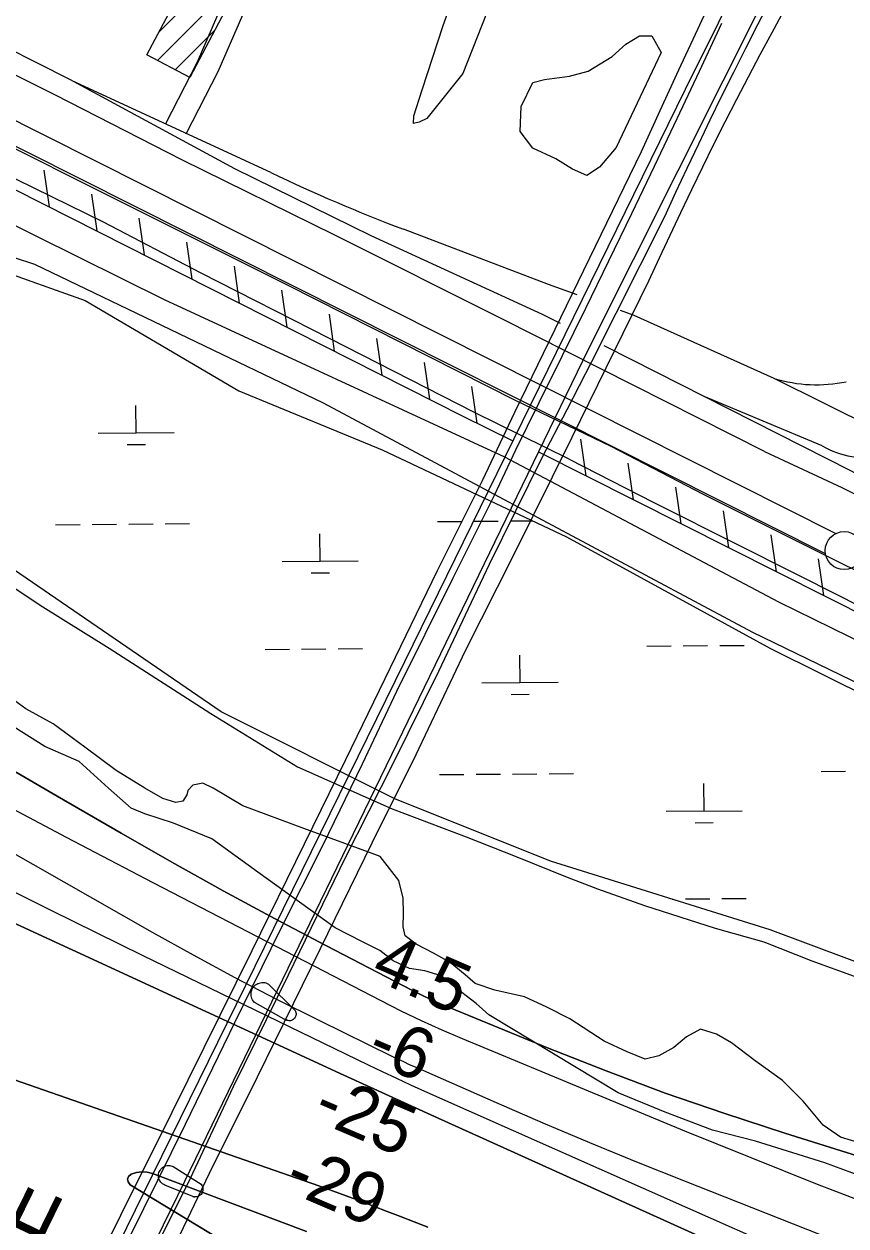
# Model space of a CAD drawing. Extents: x 3567028 to 3605064, y 510945 to 536587.
# Drawn here: x 3584827 to 3585908, y 526486 to 528066 of the extents above; entities that cross this region are included whole.
import ezdxf

# ---------------------------------------------------------------- set-up
doc = ezdxf.new("R2010")
doc.units = 0
for name, color, linetype in [('V-BLDG-OTLN', 7, 'Continuous'), ('V-BRDG-IDEN', 7, 'Continuous'), ('V-BRDG-OTLN', 7, 'Continuous'), ('V-CHAN-DOCK', 7, 'Continuous'), ('V-FLOD-BASE', 7, 'Continuous'), ('V-LEVE-TOET', 7, 'Continuous'), ('V-RIVR-EDGE', 7, 'Continuous'), ('V-RIVR-RANG', 7, 'Continuous'), ('V-ROAD-CNTR', 7, 'Continuous'), ('V-RRAP-FSHR', 7, 'Continuous'), ('V-SITE-VEGE', 7, 'Continuous'), ('V-SURV-LINE', 7, 'Continuous'), ('V-TOPO-DPTH', 7, 'Continuous'), ('V-TOPO-MINR', 7, 'Continuous'), ('V-TOPO-WATR', 7, 'Continuous'), ('V-WETL-SWMP', 7, 'Continuous')]:
    doc.layers.add(name, color=color, linetype=linetype)

msp = doc.modelspace()

# ---------------------------------------------------------------- linework, layer by layer
at = {"layer": 'V-BLDG-OTLN'}
for p, q in [((3585004, 528054.7), (3585074.8, 528125.5)), ((3585002.6, 528017.9), (3585089.1, 528104.4)), ((3585025.7, 528005.7), (3585077.9, 528057.8))]:
    msp.add_line(p, q, dxfattribs=at)
msp.add_lwpolyline([(3585099.6, 528098.9), (3585045, 527995.5), (3584988.5, 528025.3), (3585042.7, 528127.9)], dxfattribs=at)
at = {"layer": 'V-BRDG-OTLN'}
for points in [[(3584878.4, 526347.8), (3584954.3, 526500.4), (3585022, 526635.6), (3585126.9, 526848.3), (3585195.7, 526988.4), (3585250.2, 527099), (3585302.1, 527205.6), (3585370.9, 527347.8), (3585430, 527465.9), (3585472.3, 527555.5), (3585638.8, 527898.5), (3585663.3, 527952.1), (3585688, 528005.7), (3585712.8, 528059.2), (3585737.7, 528112.6)], [(3585439.1, 527355.7), (3585508.3, 527496.1), (3585541, 527559.3), (3585573.5, 527622.5), (3585605.8, 527685.9), (3585637.8, 527749.4), (3585669.5, 527813), (3585684.2, 527844.8), (3585699, 527876.6), (3585714.1, 527908.2), (3585729.3, 527939.8), (3585744.7, 527971.3), (3585760.3, 528002.7), (3585776, 528034), (3585792, 528065.3), (3585808.1, 528096.4)], [(3585826, 528083.5), (3585810.2, 528054.4), (3585794.5, 528025.2), (3585779, 527995.9), (3585763.7, 527966.5), (3585748.6, 527937), (3585733.7, 527907.3), (3585719, 527877.6), (3585704.5, 527847.8), (3585690.1, 527817.9), (3585676, 527787.9), (3585662, 527757.9), (3585648.3, 527727.7), (3585547.4, 527522.4), (3585470, 527366.7), (3585407.3, 527242.1), (3585342.1, 527105.4), (3585284.6, 526989.3), (3585216.3, 526850.2), (3585133.8, 526681.5), (3585070.7, 526554.9), (3585007, 526422.2)], [(3584927.4, 526393.9), (3584984.5, 526509.1), (3585039.6, 526619.8), (3585104.2, 526753.3), (3585163.8, 526874.9), (3585220.4, 526987.1), (3585271.9, 527093.3), (3585317.4, 527189.1), (3585391.1, 527338.1), (3585445.7, 527446.8), (3585473.5, 527506.3), (3585504.4, 527568.2), (3585535.1, 527630.2), (3585565.6, 527692.3), (3585596, 527754.5), (3585626.1, 527816.7), (3585656, 527879.1), (3585685.8, 527941.6), (3585715.3, 528004.1), (3585744.7, 528066.8)], [(3584983.4, 526423.4), (3585042.5, 526541.5), (3585102.6, 526669.6), (3585174.9, 526816.1), (3585249.6, 526970.5), (3585311.8, 527093.1), (3585372.4, 527215.2), (3585439.1, 527355.7)]]:
    msp.add_lwpolyline(points, dxfattribs=at)
at = {"layer": 'V-CHAN-DOCK'}
for points in [[(3585172.3, 526756.3), (3585130.9, 526779.2), (3585129.6, 526780.4), (3585128.5, 526781.8), (3585127.5, 526783.4), (3585126.7, 526785), (3585126.1, 526786.7), (3585125.8, 526788.5), (3585125.6, 526790.3), (3585125.6, 526792.1), (3585125.9, 526793.9), (3585126.4, 526795.6), (3585127, 526797.3), (3585127.9, 526798.9), (3585129, 526800.4), (3585130.2, 526801.7), (3585131.5, 526802.9), (3585133, 526803.9), (3585134.6, 526804.8), (3585136.3, 526805.4), (3585138.1, 526805.8), (3585139.9, 526806.1), (3585141.7, 526806.1), (3585143.5, 526805.9), (3585145.2, 526805.5), (3585146.9, 526804.9), (3585148.6, 526804.1), (3585182.7, 526770.3), (3585183.5, 526769.2), (3585184.1, 526768), (3585184.5, 526766.7), (3585184.7, 526765.4), (3585184.8, 526764.1), (3585184.6, 526762.8), (3585184.2, 526761.5), (3585183.6, 526760.3), (3585182.9, 526759.2), (3585182, 526758.2), (3585181, 526757.4), (3585179.8, 526756.7), (3585178.6, 526756.2), (3585177.3, 526755.9), (3585175.9, 526755.9), (3585174.6, 526756), (3585173.3, 526756.3), (3585172.1, 526756.8)], [(3585051.2, 526523.9), (3585012.2, 526539.7), (3585010.7, 526540.4), (3585009.3, 526541.3), (3585008.1, 526542.4), (3585006.9, 526543.6), (3585005.9, 526545), (3585005.1, 526546.4), (3585004.5, 526548), (3585004.1, 526549.6), (3585003.9, 526551.2), (3585003.9, 526552.9), (3585004.1, 526554.6), (3585004.5, 526556.2), (3585005.1, 526557.8), (3585005.9, 526559.2), (3585006.8, 526560.6), (3585007.9, 526561.8), (3585009.2, 526562.9), (3585010.6, 526563.8), (3585012.1, 526564.6), (3585013.7, 526565.1), (3585015.3, 526565.5), (3585017, 526565.6), (3585018.7, 526565.6), (3585020.3, 526565.3), (3585021.9, 526564.8), (3585023.4, 526564.1), (3585059.8, 526540.9), (3585060.7, 526539.7), (3585061.5, 526538.4), (3585062, 526537), (3585062.3, 526535.6), (3585062.4, 526534.1), (3585062.3, 526532.7), (3585061.9, 526531.2), (3585061.4, 526529.9), (3585060.7, 526528.6), (3585059.8, 526527.4), (3585058.7, 526526.4), (3585057.5, 526525.6), (3585056.2, 526524.9), (3585054.8, 526524.5), (3585053.3, 526524.2), (3585051.9, 526524.2), (3585050.4, 526524.4), (3585049, 526524.8)]]:
    msp.add_lwpolyline(points, close=True, dxfattribs=at)
at = {"layer": 'V-FLOD-BASE'}
for points in [[(3582067.9, 529075.6), (3582390.6, 528943.1), (3582813.9, 528766.3), (3583236.6, 528590.2), (3583544.8, 528463.3), (3583628.2, 528428), (3583676.5, 528412.7), (3583853.7, 528359.9), (3583920.6, 528338.4), (3583993, 528309.9), (3584101.2, 528261.4), (3584270.1, 528174.8), (3584552.1, 528034.2), (3584908.4, 527855.4), (3585173.1, 527723.1), (3585473, 527571.4), (3585598.5, 527510.8)], [(3585598.5, 527510.8), (3585720.1, 527448.1), (3585840.9, 527387.5), (3585981.5, 527317.2), (3586090.3, 527262.9), (3586177.2, 527217.9), (3586257, 527178), (3586332.7, 527140.1), (3586408, 527101), (3586484.1, 527063.1), (3586580.5, 527015.9), (3586678.1, 526965.9), (3586788.5, 526910.3), (3586899.4, 526854.4), (3587009.8, 526797.2), (3587129.4, 526739.1), (3587234.4, 526686.1), (3587359.8, 526623.8)]]:
    msp.add_lwpolyline(points, dxfattribs=at)
at = {"layer": 'V-LEVE-TOET'}
for points in [[(3585800.6, 527504), (3585456.1, 527677.8), (3585235.8, 527788.4), (3585034.7, 527887.3), (3584868.3, 527972.4), (3584648.8, 528081.5), (3584466.7, 528175.6), (3584328.5, 528266.6), (3584153.9, 528352.1), (3584057.8, 528396.8), (3583943.7, 528438.9), (3583778.9, 528490.4), (3583702.3, 528503.4), (3583587.4, 528539.2), (3583433.9, 528602.8), (3583298.3, 528659.7), (3583120.2, 528732.7), (3582964.7, 528798.7), (3582761.2, 528883.9), (3582560, 528967.9), (3582369.7, 529046.8), (3582210, 529111.6), (3582064.8, 529177.9)], [(3585544, 527493.7), (3585419.4, 527555.3), (3585229.6, 527652.2), (3585059.3, 527738.9), (3584931.6, 527805.6), (3584725.8, 527906.4), (3584560.1, 527988.8), (3584318.8, 528108.5), (3584129.3, 528205.4), (3584045.3, 528249.3), (3583951.6, 528290.5), (3583911, 528308.6), (3583847.3, 528329.4), (3583708.6, 528369.5)], [(3585544, 527493.7), (3585654.1, 527437.3), (3585767.8, 527380.5), (3585904.3, 527311.5), (3586020.1, 527251.8), (3586143.8, 527192.4), (3586262.9, 527128.9), (3586361.8, 527080.1), (3586459.4, 527034.2), (3586528.1, 526999.7), (3586615.8, 526956.3), (3586715, 526906.3), (3586804.8, 526858.3), (3586895.4, 526812.9), (3586998.8, 526760.7), (3587096, 526711.1), (3587210.1, 526655.1), (3587296.2, 526610.9)], [(3585800.6, 527504), (3585902.4, 527456.8), (3586009.5, 527403.8), (3586145.2, 527337.3), (3586258.5, 527279.2), (3586373.1, 527220.3), (3586475.7, 527168.6), (3586573.3, 527118.9), (3586670.1, 527068), (3586785, 527007.1), (3586874.3, 526955.4), (3586919, 526931), (3586960, 526913.3), (3586991, 526902.3), (3587048.1, 526880.7), (3587077.1, 526867.7), (3587199.5, 526801.3), (3587323.2, 526735.3)]]:
    msp.add_lwpolyline(points, dxfattribs=at)
at = {"layer": 'V-RIVR-EDGE'}
for points in [[(3585334, 526824.6), (3585312.6, 526834.4), (3585294.8, 526848), (3585272.2, 526859.7), (3585236.1, 526878.1), (3585134.5, 526951.3), (3585074, 526995), (3585023.8, 527015.3), (3584985.8, 527027.7), (3584968.1, 527035), (3584938.1, 527061.5), (3584899.6, 527096.5), (3584854.3, 527116.2), (3584753.4, 527179.6)], [(3586130.9, 526467.9), (3586052.5, 526500.5), (3585992.5, 526531.3), (3585915.4, 526556), (3585879.9, 526569), (3585788.7, 526597.4), (3585732.3, 526612.2), (3585669.9, 526635.7), (3585608.1, 526660.9), (3585438, 526763.7), (3585421.5, 526778.4), (3585389.7, 526803), (3585375.6, 526814.7), (3585354.2, 526821.5), (3585334, 526824.6)]]:
    msp.add_lwpolyline(points, dxfattribs=at)
at = {"layer": 'V-ROAD-CNTR'}
for points in [[(3587306.2, 531259), (3586754.9, 530134.8), (3586369, 529338.2), (3585957, 528504.3), (3585696.4, 527979.8), (3585493, 527565.5)], [(3587344.1, 531242.8), (3586812, 530145.3), (3586563.1, 529653), (3586317.5, 529145.1), (3586066.9, 528651.8), (3585863.7, 528225.8), (3585568.9, 527637.9), (3585525.1, 527547.7)], [(3584887.2, 527992.8), (3584760.1, 528057), (3584640.4, 528117.2), (3584312.5, 528284.6), (3584113.6, 528394.3)], [(3585040.2, 527921.4), (3585082.3, 528003.3), (3585130.8, 528115.4), (3585145.2, 528145), (3585155.2, 528170.5), (3585161.3, 528193.7), (3585161.5, 528216.6), (3585153.4, 528233.4), (3585133.7, 528249.1), (3585112.6, 528248.4), (3585093.8, 528246.3), (3585078.4, 528228.2), (3585069.9, 528210.7), (3585068.9, 528190.9), (3585070.8, 528172.1), (3585079.4, 528151.8), (3585089.1, 528135.1), (3585100, 528120.8)], [(3585013.5, 527935.1), (3585055.2, 528016.1), (3585100.4, 528120.7)], [(3585532.4, 527672.1), (3585508.9, 527684.1), (3585283.4, 527787.6), (3585104.1, 527875.4), (3584887.2, 527992.8)], [(3585151.7, 527870.8), (3584890.6, 527991)], [(3585554.3, 527710.1), (3585516.8, 527723.7), (3585326, 527796.1)], [(3585813.5, 527600), (3585629.1, 527682.8), (3585611.5, 527689.3)], [(3586903, 526969), (3586583.5, 527131.1), (3586151, 527350.4), (3585914.1, 527478.7), (3585626, 527624.3), (3585589.8, 527642.8)], [(3586146.9, 527434.3), (3585813.5, 527600)], [(3585876.4, 527511.3), (3585721.4, 527576.1)], [(3585493, 527565.5), (3585327.3, 527227.7), (3584995.7, 526552.3), (3583985.4, 524494)], [(3585525.1, 527547.7), (3585038.1, 526544.5), (3584025.1, 524473)]]:
    msp.add_lwpolyline(points, dxfattribs=at)
for centre, radius, start, end in [((3586131.7, 529917.9), 2269.7, 244.4188, 249.208), ((3585869.3, 527782.2), 190.5, 252.9657, 281.7789), ((3585933.6, 527610.8), 114.8, 240.1408, 281.706)]:
    msp.add_arc(centre, radius, start, end, dxfattribs=at)
at = {"layer": 'V-RRAP-FSHR'}
for p, q in [((3584860.7, 527825.5), (3584853.8, 527873.8)), ((3584923.2, 527793.9), (3584916.3, 527842.2)), ((3584985.7, 527762.3), (3584978.7, 527810.6)), ((3585048.1, 527730.7), (3585041.2, 527779)), ((3585110.6, 527699.1), (3585103.7, 527747.4)), ((3585173.1, 527667.5), (3585166.1, 527715.9)), ((3585235.5, 527635.9), (3585228.6, 527684.3)), ((3585298, 527604.3), (3585291.1, 527652.7)), ((3585360.5, 527572.8), (3585353.5, 527621.1)), ((3585423, 527541.2), (3585415.8, 527589.5)), ((3585566.1, 527471.9), (3585559.1, 527520.2)), ((3585628.6, 527440.4), (3585621.6, 527488.8)), ((3585691.2, 527409), (3585684.1, 527457.3)), ((3585753.7, 527377.5), (3585746.7, 527425.8)), ((3585816.2, 527346), (3585809.2, 527394.4)), ((3585878.8, 527314.6), (3585871.7, 527362.9))]:
    msp.add_line(p, q, dxfattribs=at)
for points in [[(3584298.5, 528109.8), (3585404.2, 527550.6), (3585469.6, 527517.9)], [(3585503.6, 527503.4), (3586446, 527029.2), (3587521.2, 526494.8)]]:
    msp.add_lwpolyline(points, dxfattribs=at)
at = {"layer": 'V-SITE-VEGE'}
for points in [[(3585441.6, 528096.3), (3585404, 528000.7), (3585356.5, 527941.8), (3585346.5, 527936.8), (3585339, 527935.2), (3585339.8, 527945.1), (3585350.7, 527979.2), (3585378.3, 528064), (3585461.1, 528294.2)], [(3584185.4, 528109.2), (3584389.9, 528011.8), (3585011.2, 527703.6), (3585458.6, 527496.8), (3585818.9, 527306.2), (3585981.5, 527226.6)], [(3586058.2, 527133.6), (3585785.2, 527266.2), (3585221, 527567.7), (3584841.3, 527749.9), (3584733.8, 527784.7)], [(3584766, 527356.9), (3584848.5, 527302.1), (3584939, 527245.7), (3585072.8, 527159.5), (3585186.7, 527089.7), (3585311.2, 527034.2), (3585408.6, 526997.7), (3585475, 526971.3), (3585541.4, 526944.5), (3585581.1, 526929.1), (3585642.8, 526907.2), (3585735.9, 526877.4), (3585799.9, 526859.4), (3585862.8, 526834.7), (3585918.4, 526814.4)], [(3585929.7, 526594.2), (3585900.6, 526602.8), (3585877.6, 526618.5), (3585851.5, 526650.2), (3585824.2, 526677.1), (3585788.5, 526703.2), (3585757.2, 526727), (3585737.7, 526738.3), (3585716.6, 526744.8), (3585698.2, 526734.5), (3585681.4, 526720.7), (3585661.8, 526709.7), (3585643.8, 526705.4), (3585620.3, 526715.1), (3585589.7, 526728.9), (3585544.5, 526758.3), (3585514.3, 526773.7), (3585484.9, 526787.4), (3585445.9, 526796.1), (3585420.4, 526804.6), (3585407.3, 526816.3), (3585387.5, 526832.4), (3585365.3, 526844.5), (3585342.6, 526856.6), (3585328.3, 526867.5), (3585325.6, 526879.4), (3585325.8, 526897.4), (3585325.5, 526916.9), (3585319.7, 526940.1), (3585295.2, 526971.7), (3585284.8, 526975.8), (3585195, 527008.3), (3585114.6, 527038.4), (3585075.7, 527061.4), (3585062.2, 527068.2), (3585049, 527065.5), (3585042.6, 527058.4), (3585041, 527052.8), (3585036.1, 527044.5), (3585026.5, 527042.6), (3585009.8, 527047.9), (3584986, 527061.6), (3584948.3, 527084.6), (3584907, 527115.5), (3584865.4, 527146.1), (3584829.6, 527165.9), (3584795.5, 527190.5)]]:
    msp.add_lwpolyline(points, dxfattribs=at)
msp.add_lwpolyline([(3585664.8, 528028.4), (3585605.6, 527903.7), (3585583.6, 527877.7), (3585567.2, 527866.8), (3585548, 527875.1), (3585526.1, 527888.8), (3585495.9, 527902.6), (3585479.5, 527924.6), (3585480.9, 527957.5), (3585496.1, 527989), (3585511.2, 527993.1), (3585544.1, 527997.1), (3585568.8, 528003.9), (3585600.4, 528023.1), (3585618.2, 528039.5), (3585636.1, 528050.4), (3585652.5, 528050.4)], close=True, dxfattribs=at)
at = {"layer": 'V-SURV-LINE'}
for points in [[(3584075.3, 528311.7), (3585894.4, 527396.1)], [(3585880.9, 527369.3), (3584061.8, 528284.9)]]:
    msp.add_lwpolyline(points, dxfattribs=at)
msp.add_circle((3585905.5, 527373.7), 25, dxfattribs=at)
at = {"layer": 'V-TOPO-DPTH'}
for points in [[(3582892.5, 527538.4), (3583965.4, 527211.6), (3583981, 527207.9), (3583996.5, 527203.9), (3584162.8, 527158.6), (3584198.8, 527148), (3584234.5, 527136.4), (3584269.7, 527123.5), (3584304.5, 527109.5), (3584393.8, 527071.7), (3584472.9, 527037.7), (3584551.8, 527003.3), (3584630.3, 526968.2), (3584708.6, 526932.5), (3585247.7, 526684.3), (3585277.5, 526670.6), (3585307.2, 526657), (3585337, 526643.4), (3585366.8, 526629.9), (3586440.2, 526144.8)], [(3586440.2, 526144.8), (3585366.8, 526629.9), (3585337, 526643.4), (3585307.2, 526657), (3585277.5, 526670.6), (3585247.7, 526684.3), (3584708.6, 526932.5), (3584630.3, 526968.2), (3584551.8, 527003.3), (3584472.9, 527037.7), (3584393.8, 527071.7), (3584304.5, 527109.5), (3584269.7, 527123.5), (3584234.5, 527136.4), (3584198.8, 527148), (3584162.8, 527158.6), (3583996.5, 527203.9), (3583981, 527207.9), (3583965.4, 527211.6), (3582892.5, 527538.4)], [(3584762.2, 527114.1), (3584870.8, 527051.1), (3584954.7, 527002.4), (3585021.6, 526964.2), (3585088.9, 526926.7), (3585156.6, 526890.1), (3585224.8, 526854.2), (3585336.8, 526796.1), (3585349.3, 526789.9), (3585361.8, 526783.8), (3585374.5, 526778.2), (3585387.4, 526772.7), (3585515.2, 526720.4), (3585592.4, 526689.9), (3585670.1, 526660.8), (3585748.5, 526633.7), (3585827.3, 526607.9), (3586934.5, 526261.2)], [(3586488.5, 526231.5), (3585694.5, 526545.3), (3585632.7, 526570.1), (3585571, 526595.4), (3585509.6, 526621.4), (3585448.4, 526647.9), (3585341.9, 526694.6), (3585334.1, 526698), (3585326.4, 526701.6), (3585318.7, 526705.2), (3585311.1, 526708.9), (3585215, 526756.1), (3585159.6, 526783.9), (3585104.6, 526812.4), (3585050.1, 526841.9), (3584995.9, 526872), (3584801.3, 526982.7)], [(3586488.5, 526231.5), (3585694.5, 526545.3), (3585632.7, 526570.1), (3585571, 526595.4), (3585509.6, 526621.4), (3585448.4, 526647.9), (3585341.9, 526694.6), (3585334.1, 526698), (3585326.4, 526701.6), (3585318.7, 526705.2), (3585311.1, 526708.9), (3585215, 526756.1), (3585159.6, 526783.9), (3585104.6, 526812.4), (3585050.1, 526841.9), (3584995.9, 526872), (3584801.3, 526982.7)], [(3584677.1, 526725.7), (3585214.8, 526538.7), (3585232.8, 526532.3), (3585250.8, 526525.8), (3585268.7, 526519.1), (3585286.6, 526512.3), (3585304.4, 526505.3), (3585322.2, 526498.4), (3585340.1, 526491.5), (3585357.9, 526484.5)], [(3585357.9, 526484.5), (3585340.1, 526491.5), (3585322.2, 526498.4), (3585304.4, 526505.3), (3585286.6, 526512.3), (3585268.7, 526519.1), (3585250.8, 526525.8), (3585232.8, 526532.3), (3585214.8, 526538.7), (3584677.1, 526725.7)], [(3585158.9, 526423.7), (3584966.8, 526540.3), (3584964.1, 526544), (3584963, 526547.6), (3584964.5, 526551), (3584967.8, 526554.3), (3584974.9, 526556.4), (3584981.9, 526557.4), (3584989.1, 526556.8), (3584996.2, 526555), (3585198.5, 526479)], [(3585198.5, 526479), (3584996.2, 526555), (3584989.1, 526556.8), (3584981.9, 526557.4), (3584974.9, 526556.4), (3584967.8, 526554.3), (3584964.5, 526551), (3584963, 526547.6), (3584964.1, 526544), (3584966.8, 526540.3), (3585158.9, 526423.7)]]:
    msp.add_lwpolyline(points, dxfattribs=at)
at = {"layer": 'V-TOPO-MINR'}
for points in [[(3586045.4, 526473.5), (3585870.2, 526540.6), (3585696, 526610.5), (3585403.8, 526731.9), (3585376.7, 526743.5), (3585349.7, 526755.7), (3585323.1, 526768.5), (3585296.7, 526781.8), (3584996.8, 526937.2), (3584883, 526996.8), (3584769.5, 527056.9), (3584656.4, 527117.9), (3584543.7, 527179.4), (3584371, 527274.6), (3584344.8, 527288.9), (3584318.5, 527303.1), (3584292.1, 527317), (3584265.6, 527330.7), (3583708.8, 527616.6)], [(3585826.7, 526453.5), (3585699.8, 526509.3), (3585354.2, 526662.9), (3585335.6, 526671.3), (3585317.1, 526679.8), (3585298.6, 526688.5), (3585280.2, 526697.4), (3584982.8, 526841.7), (3584862.9, 526900.5), (3584743.4, 526960.1), (3584624.4, 527020.6), (3584505.8, 527081.9), (3584313.3, 527182.4), (3584291.1, 527193.8), (3584268.9, 527205), (3584246.5, 527216), (3584224, 527226.8), (3582931.9, 527600.3)], [(3586440.2, 526144.8), (3585366.8, 526629.9), (3585337, 526643.4), (3585307.2, 526657), (3585277.5, 526670.6), (3585247.7, 526684.3), (3584708.6, 526932.5), (3584630.3, 526968.2), (3584551.8, 527003.3), (3584472.9, 527037.7), (3584393.8, 527071.7), (3584304.5, 527109.5), (3584269.7, 527123.5), (3584234.5, 527136.4), (3584198.8, 527148), (3584162.8, 527158.6), (3583996.5, 527203.9), (3583981, 527207.9), (3583965.4, 527211.6), (3582892.5, 527538.4)], [(3586488.5, 526231.5), (3585694.5, 526545.3), (3585632.7, 526570.1), (3585571, 526595.4), (3585509.6, 526621.4), (3585448.4, 526647.9), (3585341.9, 526694.6), (3585334.1, 526698), (3585326.4, 526701.6), (3585318.7, 526705.2), (3585311.1, 526708.9), (3585215, 526756.1), (3585159.6, 526783.9), (3585104.6, 526812.4), (3585050.1, 526841.9), (3584995.9, 526872), (3584801.3, 526982.7)], [(3585357.9, 526484.5), (3585340.1, 526491.5), (3585322.2, 526498.4), (3585304.4, 526505.3), (3585286.6, 526512.3), (3585268.7, 526519.1), (3585250.8, 526525.8), (3585232.8, 526532.3), (3585214.8, 526538.7), (3584677.1, 526725.7)], [(3585198.5, 526479), (3584996.2, 526555), (3584989.1, 526556.8), (3584981.9, 526557.4), (3584974.9, 526556.4), (3584967.8, 526554.3), (3584964.5, 526551), (3584963, 526547.6), (3584964.1, 526544), (3584966.8, 526540.3), (3585158.9, 526423.7)]]:
    msp.add_lwpolyline(points, dxfattribs=at)
at = {"layer": 'V-TOPO-WATR'}
msp.add_lwpolyline([(3586934.5, 526261.2), (3585827.3, 526607.9), (3585748.5, 526633.7), (3585670.1, 526660.8), (3585592.4, 526689.9), (3585515.2, 526720.4), (3585387.4, 526772.7), (3585374.5, 526778.2), (3585361.8, 526783.8), (3585349.3, 526789.9), (3585336.8, 526796.1), (3585224.8, 526854.2), (3585156.6, 526890.1), (3585088.9, 526926.7), (3585021.6, 526964.2), (3584954.7, 527002.4), (3584870.8, 527051.1), (3584762.2, 527114.1)], dxfattribs=at)
at = {"layer": 'V-WETL-SWMP'}
for p, q in [((3584974.5, 527528.6), (3584974.2, 527564.6)), ((3584924.5, 527528.2), (3585024.5, 527529.1)), ((3584962.6, 527513.1), (3584986.6, 527513.3)), ((3585370.6, 527411.9), (3585402.6, 527412.2)), ((3585418.6, 527412.3), (3585450.6, 527412.6)), ((3585466.6, 527412.7), (3585495.2, 527413)), ((3584868.7, 527407.7), (3584900.7, 527408)), ((3584916.7, 527408.1), (3584948.7, 527408.4)), ((3584964.7, 527408.5), (3584996.7, 527408.8)), ((3585012.7, 527408.9), (3585044.7, 527409.2)), ((3585216.4, 527359.9), (3585216.1, 527395.9)), ((3585166.4, 527359.5), (3585266.4, 527360.3)), ((3585204.6, 527344.4), (3585228.6, 527344.6)), ((3585144, 527243.9), (3585176, 527244.1)), ((3585192, 527244.3), (3585224, 527244.5)), ((3585240, 527244.7), (3585272, 527244.9)), ((3585645.9, 527248.1), (3585677.9, 527248.4)), ((3585693.9, 527248.5), (3585725.9, 527248.8)), ((3585741.9, 527248.9), (3585773.9, 527249.2)), ((3585479.2, 527200.3), (3585478.9, 527236.2)), ((3585429.2, 527199.8), (3585529.2, 527200.7)), ((3585467.4, 527184.7), (3585491.4, 527184.9)), ((3585373.4, 527079.3), (3585405.4, 527079.6)), ((3585421.4, 527079.7), (3585453.4, 527080)), ((3585469.4, 527080.1), (3585501.4, 527080.4)), ((3585517.4, 527080.5), (3585549.4, 527080.8)), ((3585875.3, 527083.5), (3585907.3, 527083.8)), ((3585721.2, 527031.5), (3585720.9, 527067.5)), ((3585671.2, 527031.1), (3585771.2, 527031.9)), ((3585709.3, 527016), (3585733.3, 527016.2)), ((3585679.2, 526915.7), (3585680.7, 526915.7)), ((3585696.7, 526915.9), (3585728.7, 526916.2)), ((3585744.7, 526916.3), (3585776.7, 526916.6))]:
    msp.add_line(p, q, dxfattribs=at)
msp.add_lwpolyline([(3586070.8, 526777), (3585808.1, 526875.3), (3585519.3, 526965.7), (3585314.8, 527047.6), (3585086.5, 527161.7), (3584736.3, 527401.3), (3584544.2, 527525.2), (3584505.8, 527583.8), (3584484.6, 527644.9), (3584476.8, 527683.5), (3584483.5, 527731.3), (3584499.5, 527759.2), (3584523.4, 527773.7), (3584559.3, 527783), (3584632.4, 527781.5), (3584709.5, 527768.1), (3584786.5, 527745.3), (3584907.3, 527702.6), (3585109.5, 527583.7), (3585297.9, 527506), (3585540.3, 527391.7), (3585808.7, 527245.2), (3586149.2, 527076)], dxfattribs=at)

# ---------------------------------------------------------------- texts
at = {"layer": 'V-BRDG-IDEN'}
msp.add_text('HALE BOGGS BRIDGE', height=83, rotation=63.9326, dxfattribs=at).set_placement((3584359, 525461.9))
at = {"layer": 'V-RIVR-RANG'}
for s, rotation, p in [('4.5', 336.5783, (3585280.8, 526812.1)), ('-6', 336.8616, (3585274.5, 526705.6)), ('-25', 336.8616, (3585204, 526627)), ('-29', 336.8616, (3585166.1, 526534.4))]:
    msp.add_text(s, height=67, rotation=rotation, dxfattribs=at).set_placement(p)

doc.saveas('drawing.dxf')
